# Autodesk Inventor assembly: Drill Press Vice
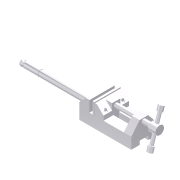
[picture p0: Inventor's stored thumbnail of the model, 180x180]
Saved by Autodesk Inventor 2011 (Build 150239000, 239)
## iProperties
Created: 2009-05
Part Number: Drill Press Vice
Document SubType Name: Assembly
Designer: Sham
Author: Sham
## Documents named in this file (9)
- C:\Users\CADSoft\Desktop\part files\c12-inv-2011-prt\c12-tut03-inv\Drill Press Vice.iam
- C:\Inventor_2011\tutorials\c12\Drill Press Vice\Base.ipt
- C:\Inventor_2011\tutorials\c12\Drill Press Vice\Safety Handle.ipt
- C:\Inventor_2011\tutorials\c12\Drill Press Vice\Jaw Face.ipt
- C:\Inventor_2011\tutorials\c12\Drill Press Vice\Movable Jaw.ipt
- C:\Inventor_2011\tutorials\c12\Drill Press Vice\Cap Screw.ipt
- C:\Inventor_2011\tutorials\c12\Drill Press Vice\Clamp Screw Handle.ipt
- C:\Inventor_2011\tutorials\c12\Drill Press Vice\Clamp Screw.ipt
- C:\Inventor_2011\tutorials\c12\Drill Press Vice\Handle Stop.ipt
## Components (10 placed, 8 different names)
1. Base:1 — Mate:1, Mate:2, Mate:3, Flush:1
2. Safety Handle:1
3. Jaw Face:1 — Mate:1, Mate:4, Flush:1
4. Movable Jaw:1 — Mate:2, Mate:3, Mate:4, Insert:2, Insert:3, Insert:4
5. Cap Screw:1 — Insert:2
6. Cap Screw:2 — Insert:3
7. Clamp Screw:1 — Insert:4, Mate:6
8. Clamp Screw Handle:1 — Mate:6, Insert:5, Insert:6
9. Handle Stop:1 — Insert:6
10. Handle Stop:2 — Insert:5
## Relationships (11: Mate 5, Insert 5, Flush 1)
- Mate:1: Base:1 ↔ Jaw Face:1
- Mate:2: Base:1 ↔ Movable Jaw:1
- Mate:3: Base:1 ↔ Movable Jaw:1
- Mate:4: Jaw Face:1 ↔ Movable Jaw:1
- Insert:2: Movable Jaw:1 ↔ Cap Screw:1
- Insert:3: Movable Jaw:1 ↔ Cap Screw:2
- Insert:4: Movable Jaw:1 ↔ Clamp Screw:1
- Mate:6: Clamp Screw:1 ↔ Clamp Screw Handle:1
- Insert:5: Clamp Screw Handle:1 ↔ Handle Stop:2
- Insert:6: Clamp Screw Handle:1 ↔ Handle Stop:1
- Flush:1: Base:1 ↔ Jaw Face:1
